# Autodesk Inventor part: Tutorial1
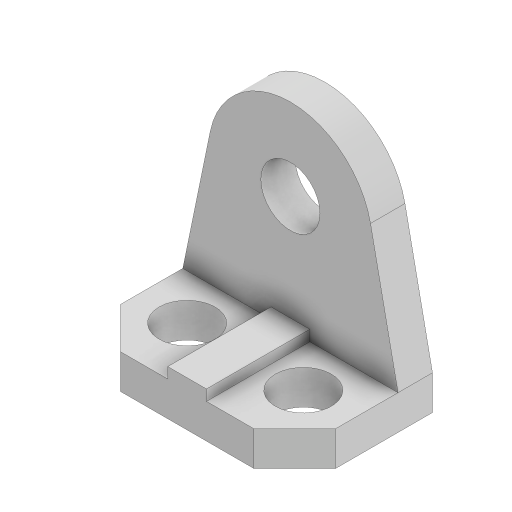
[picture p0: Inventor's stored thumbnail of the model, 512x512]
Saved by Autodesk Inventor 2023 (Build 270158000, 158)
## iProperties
Created: 2021-03
Part Number: Tutorial1
Material: Generic
Document SubType Name: Modeling
Designer: ASUS Laptop
Density: 1 g/cm^3
Appearance: Default
Author: ASUS Laptop
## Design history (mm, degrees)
sketch "Sketch1"
  geometry: L1 (0, 0)-(-200, 0); L2 (-200, 0)-(-200, 90); L3 (-200, 90)-(-162, 128); L4 (-162, 128)-(-38, 128); L5 (-38, 128)-(0, 90); L6 (0, 90)-(0, 0); L7 (-154, 74)-(-31.817, 74); C1 r 26 at (-154, 74); C2 r 26 at (-46, 74); 1 further point
  constraints: 14 end point, 2 centre point, 2 horizontal, 2 parallel, 2 perpendicular, 1 coincident, 1 equal radius, 1 point on line
  dimensions: "d0" = 128 distance between parallel lines of L4 L1; "d1" = 90 distance of L1.end L2.end; "d2" = 124 distance of L3.end L4.end; "d3" = 38 horizontal distance of L3.end L2.end; "d4" = 38 horizontal distance of L5.end L4.end; "d5" = 46 distance from line of L7.start L2; "d6" = 46 distance from line of L6 C2.centre; "d7" = 74 distance from line of L7.start L1; "d8" = 52 diameter of C2
extrude "Extrusion1" new body sketch "Sketch1" distance "d9" = 32; taper "d10" = 0 deg
sketch "Sketch2"
  geometry: L1 (200, 32)-(162, 32) reference; L2 (200, 32)-(174.418, 155.424); L3 (38, 32)-(0, 32) reference; L4 (25.582, 155.424)-(0, 32); L5 (0, 32)-(200, 32); L6 (162, 0)-(38, 0) reference; L7 (100, 0)-(100, 176.194); C1 r 27.5 at (100, 140); A1 r 76 centre (100, 140) between (174.418, 155.424) and (25.582, 155.424); 3 further points
  constraints: 8 end point, 2 centre point, 2 point on circle, 2 tangent, 1 coincident, 1 collinear, 1 midpoint, 1 vertical, 1 other
  dimensions: "d11" = 76 radius of A1; "d12" = 108 distance from line of A1.centre L5; "d13" = 55 diameter of C1
extrude "Extrusion2" join sketch "Sketch2" distance "d14" = 32; taper "d15" = 0 deg
sketch "Sketch3"
  geometry: 1 further point
sketch "Sketch4"
  geometry: L1 (0, 32)-(124, 32) reference; L2 (44, 32)-(80, 32); L3 (80, 32)-(80, 42); L4 (80, 42)-(44, 42); L5 (44, 42)-(44, 32); L6 (-38, 0)-(-38, 32) reference; 1 further point
  constraints: 8 end point, 2 parallel, 1 horizontal, 1 perpendicular, 1 point on line
  dimensions: "d16" = 36 distance of L3.end L4.end; "d17" = 10 distance of L4.end L2.start; "d18" = 82 distance between parallel lines of L5 L6
extrude "Extrusion3" join sketch "Sketch4" stored distance "d19" = 32; taper "d20" = 0 deg
body "Solid1"
